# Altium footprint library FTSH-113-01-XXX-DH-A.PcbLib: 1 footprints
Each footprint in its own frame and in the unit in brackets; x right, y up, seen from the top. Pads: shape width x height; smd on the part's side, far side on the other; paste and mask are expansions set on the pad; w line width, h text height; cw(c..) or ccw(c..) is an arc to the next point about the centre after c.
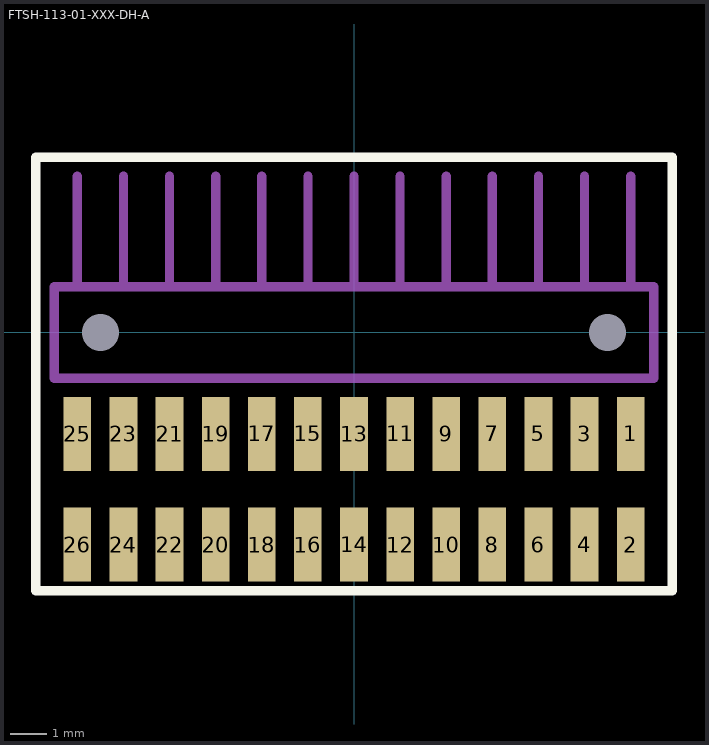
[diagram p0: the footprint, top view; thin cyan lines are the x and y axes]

## FTSH-113-01-XXX-DH-A [mil]
pads (28):
  rect 30x80 smd mask+2: 1(300,-110) 2(300,-230) 3(250,-110) 4(250,-230) 5(200,-110) 6(200,-230) 7(150,-110) 8(150,-230) 9(100,-110) 10(100,-230) 11(50,-110) 12(50,-230) 13(0,-110) 14(0,-230) 15(-50,-110) 16(-50,-230) 17(-100,-110) 18(-100,-230) 19(-150,-110) 20(-150,-230) 21(-200,-110) 22(-200,-230) 23(-250,-110) 24(-250,-230) 25(-300,-110) 26(-300,-230)
  round 0 hole 40 unplated: 27(275,0) 28(-275,0)
Top Overlay:
  lines w10: -345,-280 -345,190 345,190 345,-280 -345,-280
Mechanical 1:
  lines w10: -300,49.5 -300,169.5 ; -250,49.5 -250,169.5 ; -200,49.5 -200,169.5 ; -150,49.5 -150,169.5 ; -100,49.5 -100,169.5 ; -50,49.5 -50,169.5 ; 0,49.5 0,169.5 ; 50,49.5 50,169.5 ; 100,49.5 100,169.5 ; 150,49.5 150,169.5 ; 200,49.5 200,169.5 ; 250,49.5 250,169.5 ; 300,49.5 300,169.5 ; -325,-49.5 -325,49.5 325,49.5 325,-49.5 -325,-49.5
  text "J1" at -17.57,-18 h30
